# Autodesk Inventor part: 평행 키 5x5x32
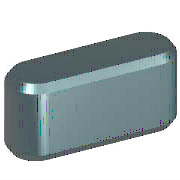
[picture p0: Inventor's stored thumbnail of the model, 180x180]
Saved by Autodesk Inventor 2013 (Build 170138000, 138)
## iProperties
Created: 2012-02
Part Number: 평행 키 5x5x32
Material: 강철, 연강
Description: 평행 키
Document SubType Name: Modeling
Standard: JIS B 1301
Designer: mdu-01
Standards Organization: JIS
Language: ko-KR
Size Designation: 5x5x32
Categories: <MemberInstance><Categories><Category DisplayName="샤프트 부품" InternalName="7f7aeb1f-a693-4053-b835-cee3144e0d98" Mnemonic="SHFT"><Category DisplayName="키" Interna
Density: 1 g/cm^3
IsCustomPart: 1
Author: mdu-01
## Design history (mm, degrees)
workplane "Work Plane1"
workplane "Work Plane2"
sketch "스케치1"
  geometry: L1 (2.5, 2.5)-(29.5, 2.5); L2 (29.5, -2.5)-(2.5, -2.5); L3 (0, 9.4)-(0, -7.4) reference; L4 (-5, 0)-(30, 0) reference; L5 (32, 0)-(32, 7); A1 r 2.5 centre (2.5, 0) between (2.5, 2.5) and (2.5, -2.5); A2 r 2.5 centre (29.5, 0) between (29.5, -2.5) and (29.5, 2.5)
  constraints: 6 end point, 5 point on circle, 4 tangent, 3 point on line, 2 centre point, 1 horizontal, 1 parallel, 1 perpendicular
  dimensions: "d0" = 2.5 radius of A1 (= 0.5 x PB); "d13" = 2.5 radius of A2 (= 0.5 x PB); "d14" = 32 distance between parallel lines of L5 L3 (= NLG)
extrude "본체1" new body sketch "스케치1" taper "d3" = 0 deg; stored distance "d4" = 10
workplane "Work Plane3"
body "Solid1"
chamfer "모따기1" distance "d8" = 0.4 (= PHH); stored, may be unused: second distance "d9" = 0.4 (= PHH), angle "d15" = 45 deg
other parameters: "d1" = -3 (= -PNT), "d2" = 2 (= PH - PNT), "NLG" = 32 [user parameter; used in 3 equation terms], "PB" = 5 [user parameter; used in 2 equation terms], "PNT" = 3 [user parameter; used in 2 equation terms], "PH" = 5 [user parameter; used in 1 equation term], "PHH" = 0.4 [user parameter; used in 2 equation terms], "d10" = 0, "d16" = 0, "d17" = 0, "d18" = 0, "WDMIN" = 12 [user parameter], "PLB2" = 32 (= NLG) [user parameter], "WDMAX" = 17 [user parameter], "PLB1" = 32 (= NLG) [user parameter], "RR" = 0.16 [user parameter], "PUEB" = 2.3 [user parameter]
